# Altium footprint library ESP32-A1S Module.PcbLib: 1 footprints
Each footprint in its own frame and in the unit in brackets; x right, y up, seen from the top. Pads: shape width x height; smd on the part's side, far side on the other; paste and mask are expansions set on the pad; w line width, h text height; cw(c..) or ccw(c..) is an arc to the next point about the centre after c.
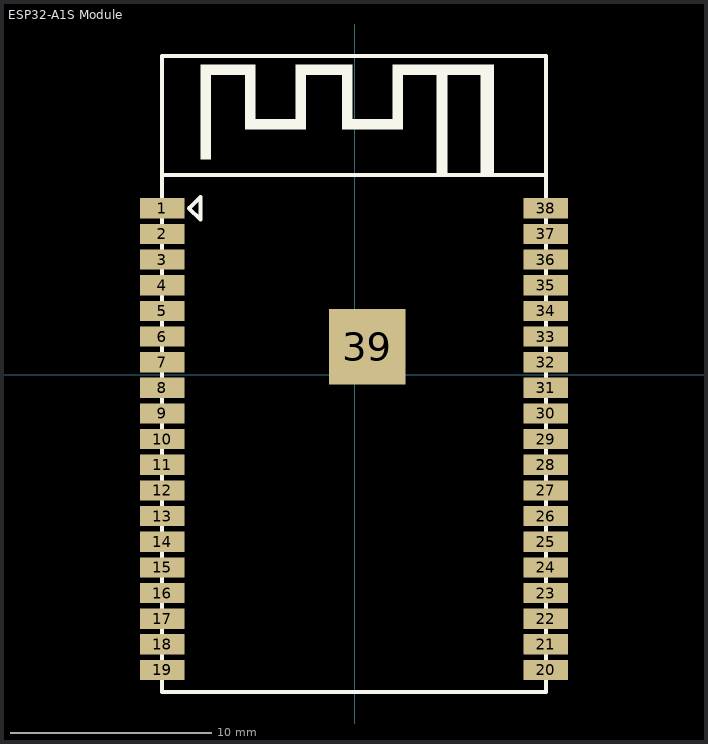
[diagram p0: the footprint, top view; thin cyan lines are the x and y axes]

## ESP32-A1S Module [mm]
pads (39):
  rect 2.2x1 smd: 1(-9.525,8.255) 2(-9.525,6.985) 3(-9.525,5.715) 4(-9.525,4.445) 5(-9.525,3.175) 6(-9.525,1.905) 7(-9.525,0.635) 8(-9.525,-0.635) 9(-9.525,-1.905) 10(-9.525,-3.175) 11(-9.525,-4.445) 12(-9.525,-5.715) 13(-9.525,-6.985) 14(-9.525,-8.255) 15(-9.525,-9.525) 16(-9.525,-10.795) 17(-9.525,-12.065) 18(-9.525,-13.335) 19(-9.525,-14.605) 20(9.475,-14.605) 21(9.475,-13.335) 22(9.475,-12.065) 23(9.475,-10.795) 24(9.475,-9.525) 25(9.475,-8.255) 26(9.475,-6.985) 27(9.475,-5.715) 28(9.475,-4.445) 29(9.475,-3.175) 30(9.475,-1.905) 31(9.475,-0.635) 32(9.475,0.635) 33(9.475,1.905) 34(9.475,3.175) 35(9.475,4.445) 36(9.475,5.715) 37(9.475,6.985) 38(9.475,8.255)
  rect 3.785x3.759 smd: 39(0.635,1.397)
Top Overlay:
  region: 6.883,15.109 6.883,9.956 6.256,9.956 6.256,15.109
  region: 6.883,14.856 6.883,15.356 1.883,15.356 1.883,12.656 -0.117,12.656 -0.117,15.356 -2.917,15.356 -2.917,12.656 -4.917,12.656 -4.917,15.356 -7.617,15.356 -7.617,10.683 -7.117,10.683 -7.117,14.856 -5.417,14.856 -5.417,12.156 -2.417,12.156 -2.417,14.856 -0.617,14.856 -0.617,12.156 2.383,12.156 2.383,14.856 4.083,14.856 4.083,9.956 4.583,9.956 4.583,14.856
  lines w0.2: -9.525,9.906 9.475,9.906 ; -8.184,8.255 -7.634,7.705 -7.634,8.805 -8.184,8.255 ; -8.184,8.255 -8.184,8.255 ; -9.525,-15.697 9.475,-15.697 9.475,15.803 -9.525,15.803 -9.525,-15.697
